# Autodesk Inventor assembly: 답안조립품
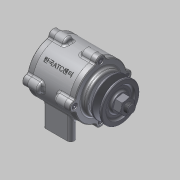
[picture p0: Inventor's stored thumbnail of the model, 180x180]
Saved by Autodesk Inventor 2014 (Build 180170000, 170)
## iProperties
Created: 2015-03
Part Number: 답안조립품
Document SubType Name: Assembly
Designer: MYHOME
Author: MYHOME
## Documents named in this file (11)
- C:\Documents and Settings\MYHOME\바탕 화면\450306V1015\답안조립품.iam
- C:\Documents and Settings\MYHOME\바탕 화면\450306V1015\본체.ipt
- C:\Documents and Settings\MYHOME\바탕 화면\450306V1015\커버.ipt
- C:\Documents and Settings\MYHOME\바탕 화면\450306V1015\커버2.ipt
- C:\Documents and Settings\MYHOME\바탕 화면\450306V1015\M 4 x 12.ipt
- C:\Documents and Settings\MYHOME\바탕 화면\450306V1015\오일실.ipt
- C:\Documents and Settings\MYHOME\바탕 화면\450306V1015\축.ipt
- C:\Documents and Settings\MYHOME\바탕 화면\450306V1015\키(4 x 4 x 12).ipt
- C:\Documents and Settings\MYHOME\바탕 화면\450306V1015\베어링 6204.ipt
- C:\Documents and Settings\MYHOME\바탕 화면\450306V1015\너트 M12x1.25.ipt
- C:\Documents and Settings\MYHOME\바탕 화면\450306V1015\V벨트풀리.ipt
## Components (14 placed, 6 different names)
1. KS B 2804 D D - 20 32 8:1
2. KS B 1311 (I) 4 x 4 x 12:1
3. KS B 2023 6204 - 20 x 47 x 14:1 — 각도:1
4. KS B 2023 6204 - 20 x 47 x 14:2 — 각도:2
5. KS B 1012 클래스 1 일반 - 미터 M12x1.25:1 — 각도:3
6. 그루브 풀리1:1
7. KS B 1003 - 미터 M 4 x 12:2
8. KS B 1003 - 미터 M 4 x 12:3
9. KS B 1003 - 미터 M 4 x 12:4
10. KS B 1003 - 미터 M 4 x 12:5
11. KS B 1003 - 미터 M 4 x 12:1
12. KS B 1003 - 미터 M 4 x 12:6
13. KS B 1003 - 미터 M 4 x 12:7
14. KS B 1003 - 미터 M 4 x 12:8
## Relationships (3: Angle 3)
- 각도:1 [Angle]: KS B 2023 6204 - 20 x 47 x 14:1
- 각도:2 [Angle]: KS B 2023 6204 - 20 x 47 x 14:2
- 각도:3 [Angle]: KS B 1012 클래스 1 일반 - 미터 M12x1.25:1
